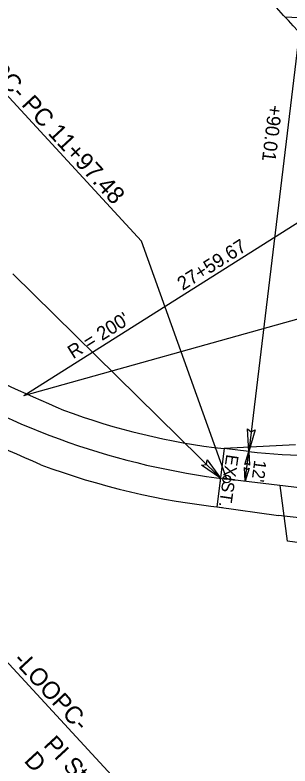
# Model space of a CAD drawing. Extents: x 1702862 to 1704514, y 793768 to 796215.
# Drawn here: x 1703635 to 1703745.4, y 794386.1 to 794687 of the extents above; entities that cross this region are included whole.
import ezdxf

# ---------------------------------------------------------------- set-up
doc = ezdxf.new("R2010")
doc.units = 0
for name, color, linetype in [('Old_Level_3', 7, 'Continuous'), ('Prop Conc 2ft 6in Curb and Gutter', 7, 'Continuous'), ('Prop Dimension', 7, 'Continuous'), ('Prop Dimension Text', 7, 'Continuous'), ('Prop DSN Text', 7, 'Continuous'), ('Prop EOT', 7, 'Continuous'), ('Prop Horizontal Alignment', 7, 'Continuous'), ('Prop Horizontal Alignment Curve and Spiral Data', 7, 'Continuous'), ('Prop Horizontal Alignment Direction Label', 7, 'Continuous'), ('Prop Horizontal Alignment Station Label', 7, 'Continuous'), ('Prop Horizontal Alignment Tick Small', 7, 'Continuous'), ('Prop Lane Lines', 7, 'Continuous'), ('Prop Leader Line Medium', 7, 'Continuous'), ('Prop Paved Shoulder', 7, 'Continuous'), ('Prop Rem of Exist Asph Pvmt', 7, 'Continuous'), ('Prop Terminator CELL', 7, 'Continuous')]:
    doc.layers.add(name, color=color, linetype=linetype)

msp = doc.modelspace()

# ---------------------------------------------------------------- linework, layer by layer
at = {"layer": 'Old_Level_3'}
for centre, major_axis, ratio, start_param, end_param in [((1703748.78, 794780.74), (195.19, -185.66), 0.998535, 5.114248, 5.3612), ((1703748.26, 794783.34), (263.08, -136.66), 0.995009, 4.834921, 5.087923)]:
    msp.add_ellipse(centre, major_axis=major_axis, ratio=ratio, start_param=start_param, end_param=end_param, dxfattribs=at)
for points in [[(1703605.37, 794553.05), (1703607.19, 794551.91), (1703654.5, 794528.75)], [(1703645.46, 794506.83), (1703595.38, 794531.44), (1703587.7, 794536.44)]]:
    msp.add_spline(points, degree=3, dxfattribs=at)
at = {"layer": 'Prop Conc 2ft 6in Curb and Gutter'}
msp.add_arc((1702985.28, 794122.36), 970.46, 32.25438, 42.65517, dxfattribs=at)
at = {"layer": 'Prop Dimension'}
for p, q in [((1703752.73, 794710.66), (1703728.81, 794512.1)), ((1703638.54, 794534.6), (1703807.68, 794641.34)), ((1703638.54, 794534.6), (1703831.2, 794588.31)), ((1703727.38, 794500.18), (1703728.81, 794512.1))]:
    msp.add_line(p, q, dxfattribs=at)
at = {"layer": 'Prop DSN Text'}
msp.add_line((1703718.99, 794513.26), (1703716.01, 794490.01), dxfattribs=at)
at = {"layer": 'Prop EOT'}
for p, q in [((1703728.81, 794512.1), (1703718.97, 794513.28)), ((1703716.01, 794490.01), (1703740.76, 794486.48)), ((1703844.62, 794474.01), (1703740.76, 794486.48))]:
    msp.add_line(p, q, dxfattribs=at)
for centre, radius, start, end in [((1702989.11, 794124.65), 1018, 14.75888, 42.70907), ((1702985.01, 794122.19), 972.78, 32.25419, 42.65174), ((1703752.73, 794710.66), 200, 263.1332, 278.4921)]:
    msp.add_arc(centre, radius, start, end, dxfattribs=at)
at = {"layer": 'Prop Horizontal Alignment'}
msp.add_line((1703836.77, 794487.04), (1703719.97, 794501.07), dxfattribs=at)
for centre, radius, start, end in [((1702989.11, 794124.65), 1000, 351.25916, 42.70907), ((1703755.73, 794798.93), 300, 238.2692, 263.1536)]:
    msp.add_arc(centre, radius, start, end, dxfattribs=at)
at = {"layer": 'Prop Horizontal Alignment Curve and Spiral Data'}
for p, q in [((1703606.08, 794682.77), (1703685.74, 794596.47)), ((1703564.23, 794501.06), (1703728.41, 794323.2))]:
    msp.add_line(p, q, dxfattribs=at)
at = {"layer": 'Prop Horizontal Alignment Direction Label'}
for p, q in [((1703744.31, 794476.19), (1703741.41, 794498.49)), ((1703750.3, 794475.45), (1703744.31, 794476.19))]:
    msp.add_line(p, q, dxfattribs=at)
at = {"layer": 'Prop Horizontal Alignment Station Label'}
msp.add_line((1703719.97, 794501.07), (1703685.74, 794596.47), dxfattribs=at)
msp.add_circle((1703719.97, 794501.07), 1.5, dxfattribs=at)
at = {"layer": 'Prop Horizontal Alignment Tick Small'}
msp.add_line((1703717.47, 794501.38), (1703716.83, 794496.42), dxfattribs=at)
at = {"layer": 'Prop Lane Lines'}
for radius, start in [(1006, 0.00687), (994, 359.40932), (980, 359.40932)]:
    msp.add_arc((1702989.11, 794124.65), radius, start, 42.70907, dxfattribs=at)
at = {"layer": 'Prop Leader Line Medium'}
msp.add_line((1703634.19, 794583.29), (1703717.47, 794501.38), dxfattribs=at)
at = {"layer": 'Prop Paved Shoulder'}
msp.add_line((1703747.55, 794514.73), (1703718.97, 794513.28), dxfattribs=at)
at = {"layer": 'Prop Rem of Exist Asph Pvmt'}
msp.add_line((1703743.47, 794686.26), (1703751.41, 794685.94), dxfattribs=at)
msp.add_spline([(1703779.68, 794644.96), (1703761.75, 794665.91), (1703731.32, 794699.4), (1703700.82, 794732.47), (1703669.4, 794765.36)], degree=3, dxfattribs=at)
at = {"layer": 'Prop Terminator CELL'}
for points in [[(1703731.42, 794520.85), (1703728.81, 794512.1), (1703728.3, 794521.27), (1703729.75, 794519.94)], [(1703727.2, 794506.86), (1703728.81, 794512.1), (1703729.07, 794506.59), (1703728.21, 794507.39)], [(1703712.14, 794508.79), (1703717.47, 794501.38), (1703709.89, 794506.58), (1703711.84, 794506.92)], [(1703728.99, 794505.41), (1703727.38, 794500.18), (1703727.12, 794505.68), (1703727.99, 794504.88)]]:
    msp.add_lwpolyline(points, close=True, dxfattribs=at)

# ---------------------------------------------------------------- texts
at = {"layer": 'Prop Dimension Text'}
for s, height, rotation, p in [('+90.01', 5.5, 263.1332, (1703736.8, 794651.24)), ('27+59.67', 5.5, 32.2542, (1703702.32, 794576.46)), ("R = 200'", 5.5, 32.2542, (1703658.37, 794549.05)), ('EXIST.', 5, 261.6644, (1703719.86, 794511.16)), ("12'", 5, 262.672, (1703731.05, 794508.88))]:
    msp.add_text(s, height=height, rotation=rotation, dxfattribs=at).set_placement(p)
at = {"layer": 'Prop Horizontal Alignment Curve and Spiral Data'}
for s, p in [('-LOOPC-', (1703633.91, 794428.2)), ('PI Sta 10+60.99', (1703646.15, 794394.26)), ('D', (1703638.35, 794387.97))]:
    msp.add_text(s, height=7, rotation=312.7091, dxfattribs=at).set_placement(p)
at = {"layer": 'Prop Horizontal Alignment Station Label'}
msp.add_text('-LOOPC- PC 11+97.48', height=7, rotation=312.7091, dxfattribs=at).set_placement((1703609.14, 794681.55))

doc.saveas('drawing.dxf')
